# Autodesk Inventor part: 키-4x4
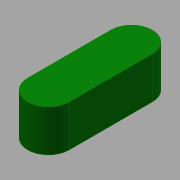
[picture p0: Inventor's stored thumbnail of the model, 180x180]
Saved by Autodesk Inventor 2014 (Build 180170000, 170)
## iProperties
Created: 2015-12
Part Number: 키-4x4
Document SubType Name: Modeling
Designer: mdu
Density: 7.86 g/cm^3
Material: 강철, 연강
Appearance: 진녹색
Author: mdu
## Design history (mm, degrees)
sketch "스케치1"
  geometry: L1 (-2, -10)-(-2, -2) reference; L2 (2, -2)-(2, -10) reference; A1 r 2 centre (0, -2) between (2, -2) and (-2, -2) reference; A2 r 2 centre (0, -10) between (-2, -10) and (2, -10) reference; 1 further point
extrude "돌출1" new body sketch "스케치1" distance "d0" = 4; taper "d1" = 0 deg
node "솔리드1"
node "참조1"
